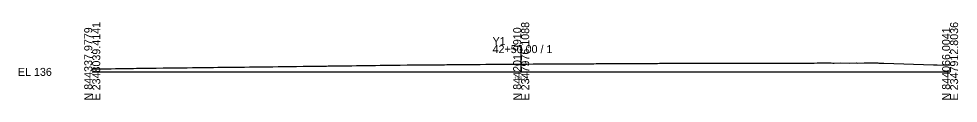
# Model space of a CAD drawing. Extents: x -26 to 2349090, y -10 to 844481.
# Drawn here: x 974.3 to 1302.8, y 7990.3 to 8017.3 of the extents above; entities that cross this region are included whole.
import ezdxf

# ---------------------------------------------------------------- set-up
doc = ezdxf.new("R2010")
doc.units = 0
for name, color, linetype in [('Exist Cross Section Cell', 7, 'Continuous'), ('Exist XS Center Line Elevation Label', 7, 'Continuous'), ('Exist XS Ground Line', 7, 'Continuous')]:
    doc.layers.add(name, color=color, linetype=linetype)

msp = doc.modelspace()

# ---------------------------------------------------------------- linework, layer by layer
at = {"layer": 'Exist Cross Section Cell'}
for p, q in [((1150, 8000), (1150, 8009.38)), ((1000, 8000), (1150, 8000)), ((1150, 8000), (1300, 8000))]:
    msp.add_line(p, q, dxfattribs=at)
at = {"layer": 'Exist XS Ground Line'}
msp.add_lwpolyline([(1000, 8001.05), (1001.63, 8001.07), (1002.7, 8001.08), (1003.56, 8001.09), (1005.29, 8001.11), (1006.62, 8001.13), (1008.18, 8001.15), (1008.81, 8001.16), (1009.54, 8001.17), (1010.81, 8001.18), (1012.18, 8001.21), (1013.45, 8001.22), (1014.41, 8001.23), (1015.45, 8001.25), (1016.32, 8001.26), (1017.48, 8001.28), (1018.39, 8001.29), (1019.89, 8001.3), (1022.33, 8001.33), (1024.77, 8001.37), (1025.18, 8001.37), (1027.36, 8001.4), (1028.34, 8001.41), (1029.79, 8001.43), (1032.52, 8001.47), (1033.19, 8001.47), (1035.1, 8001.49), (1035.62, 8001.5), (1036.76, 8001.51), (1038.38, 8001.53), (1039.18, 8001.54), (1040.55, 8001.55), (1041.11, 8001.56), (1042.39, 8001.58), (1043.9, 8001.6), (1045.03, 8001.61), (1046.14, 8001.62), (1046.66, 8001.63), (1048.04, 8001.64), (1049.39, 8001.66), (1049.89, 8001.66), (1050.98, 8001.68), (1051.79, 8001.69), (1052.17, 8001.69), (1053.21, 8001.7), (1054.94, 8001.72), (1055.54, 8001.73), (1056.87, 8001.75), (1057.7, 8001.76), (1059.33, 8001.78), (1060.44, 8001.79), (1062.78, 8001.82), (1063.19, 8001.83), (1064.96, 8001.85), (1065.96, 8001.86), (1068.72, 8001.89), (1070.62, 8001.91), (1071.46, 8001.93), (1073.81, 8001.96), (1074.21, 8001.96), (1074.66, 8001.97), (1076.98, 8002), (1078.99, 8002.02), (1079.74, 8002.03), (1080.61, 8002.04), (1081.9, 8002.06), (1082.5, 8002.07), (1083.78, 8002.08), (1085.29, 8002.1), (1085.7, 8002.11), (1086.55, 8002.12), (1088.01, 8002.13), (1089.42, 8002.16), (1090.76, 8002.17), (1092.46, 8002.2), (1093.53, 8002.21), (1095.06, 8002.23), (1096.29, 8002.25), (1096.93, 8002.25), (1098.39, 8002.27), (1099.03, 8002.28), (1100.72, 8002.3), (1101.82, 8002.31), (1102.43, 8002.32), (1104.28, 8002.35), (1104.86, 8002.36), (1107.74, 8002.38), (1110.1, 8002.42), (1110.44, 8002.42), (1112.45, 8002.43), (1112.77, 8002.43), (1114.88, 8002.46), (1115.19, 8002.46), (1117.69, 8002.48), (1119.09, 8002.5), (1120.1, 8002.5), (1121.09, 8002.52), (1122.13, 8002.53), (1123.14, 8002.53), (1124.03, 8002.54), (1125.36, 8002.55), (1126.62, 8002.57), (1127.06, 8002.57), (1128.06, 8002.58), (1128.78, 8002.58), (1129.38, 8002.59), (1130.51, 8002.6), (1132.11, 8002.61), (1132.68, 8002.62), (1133.99, 8002.62), (1134.91, 8002.63), (1135.69, 8002.64), (1137.64, 8002.65), (1139.88, 8002.67), (1140.4, 8002.67), (1142.05, 8002.69), (1143.06, 8002.69), (1144, 8002.7), (1145.87, 8002.71), (1146.21, 8002.71), (1148.62, 8002.73), (1149.62, 8002.74), (1150, 8002.74), (1151.36, 8002.75), (1152.02, 8002.76), (1154.16, 8002.77), (1156.11, 8002.78), (1156.88, 8002.79), (1157.76, 8002.79), (1159.69, 8002.8), (1161.3, 8002.81), (1162.41, 8002.81), (1163.84, 8002.82), (1164.78, 8002.82), (1165.27, 8002.83), (1166.65, 8002.84), (1168.01, 8002.85), (1169.53, 8002.86), (1170.35, 8002.86), (1170.72, 8002.86), (1171.76, 8002.87), (1173.47, 8002.87), (1174.08, 8002.88), (1175.42, 8002.88), (1176.24, 8002.89), (1176.95, 8002.89), (1179.02, 8002.9), (1179.75, 8002.9), (1181.76, 8002.91), (1182.07, 8002.92), (1184.52, 8002.93), (1185.31, 8002.93), (1187.3, 8002.94), (1190.04, 8002.95), (1190.7, 8002.95), (1193.17, 8002.97), (1194.79, 8002.97), (1195.52, 8002.98), (1195.93, 8002.98), (1197.7, 8002.99), (1198.38, 8003), (1199.9, 8003), (1200.85, 8003.01), (1202.02, 8003.01), (1202.76, 8003.01), (1203.2, 8003.01), (1203.9, 8003.01), (1205.97, 8003.02), (1207.06, 8003.02), (1208.29, 8003.03), (1209.3, 8003.02), (1209.84, 8003.02), (1211.02, 8003.03), (1211.57, 8003.04), (1212.15, 8003.04), (1213.64, 8003.04), (1214.85, 8003.04), (1216.9, 8003.05), (1217.23, 8003.06), (1217.59, 8003.06), (1219.28, 8003.06), (1220.37, 8003.06), (1223.13, 8003.08), (1224.93, 8003.07), (1225.9, 8003.08), (1226.83, 8003.09), (1228.87, 8003.09), (1231.39, 8003.09), (1233.61, 8003.09), (1234.13, 8003.1), (1234.69, 8003.1), (1236.17, 8003.1), (1236.91, 8003.1), (1238.84, 8003.1), (1239.64, 8003.1), (1239.95, 8003.1), (1240.61, 8003.1), (1241.85, 8003.1), (1242.41, 8003.11), (1244, 8003.11), (1245.2, 8003.11), (1246.54, 8003.11), (1247.94, 8003.11), (1249.2, 8003.11), (1250.72, 8003.11), (1251.24, 8003.11), (1252.48, 8003.11), (1253.46, 8003.12), (1255.03, 8003.12), (1256.25, 8003.12), (1256.92, 8003.12), (1258.36, 8003.12), (1258.94, 8003.11), (1259.46, 8003.11), (1261.76, 8003.12), (1264.68, 8003.11), (1267.26, 8003.12), (1267.61, 8003.11), (1269.94, 8003.12), (1274.71, 8003.13), (1275.03, 8003.11), (1276.84, 8003.09), (1294.24, 8002.52), (1295.47, 8002.48), (1300, 8002.31)], dxfattribs=at)

# ---------------------------------------------------------------- texts
at = {"layer": 'Exist Cross Section Cell'}
for s, p in [('E 2348039.4141', (1002.8, 7990)), ('E 2347976.1088', (1152.8, 7990)), ('E 2347912.8036', (1302.8, 7990)), ('N 844337.9779', (1000, 7990)), ('N 844201.9910', (1150, 7990)), ('N 844066.0041', (1300, 7990))]:
    msp.add_text(s, height=2.8, rotation=90, dxfattribs=at).set_placement(p)
for s, p in [('Y1', (1140, 8009.38)), ('42+50.00 / 1', (1140, 8006.58)), ('EL 136', (974, 7998.6))]:
    msp.add_text(s, height=2.8, dxfattribs=at).set_placement(p)
at = {"layer": 'Exist XS Center Line Elevation Label'}
msp.add_text('138.74', height=1.2, dxfattribs=at).set_placement((1147.55, 7997.14))

doc.saveas('drawing.dxf')
